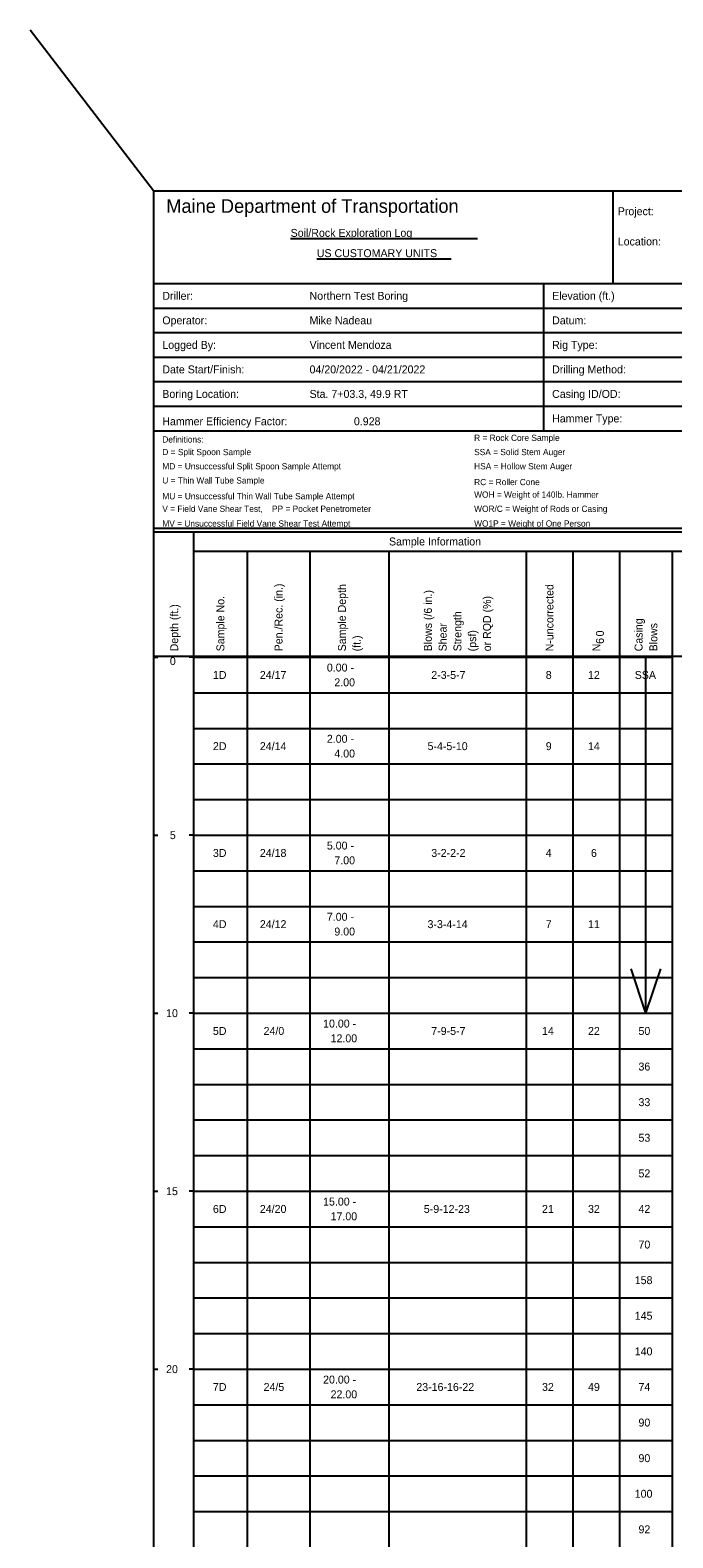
# Model space of a CAD drawing. Extents: x 9419 to 9552, y 6780 to 6865.
# Drawn here: x 9494.69 to 9512.73, y 6822.23 to 6864.58 of the extents above; entities that cross this region are included whole.
import ezdxf

# ---------------------------------------------------------------- set-up
doc = ezdxf.new("R2010")
doc.units = 0
doc.layers.add('7', color=7, linetype='Continuous')
doc.layers.add('JUNK', color=7, linetype='Continuous')

msp = doc.modelspace()

# ---------------------------------------------------------------- linework, layer by layer
at = {"layer": '7'}
for p, q in [((9502.002, 6858.729), (9507.244, 6858.729)), ((9502.736, 6858.16), (9506.51, 6858.16)), ((9511.973, 6836.968), (9511.973, 6846.968)), ((9511.973, 6836.968), (9511.556, 6838.218)), ((9511.973, 6836.968), (9512.389, 6838.218))]:
    msp.add_line(p, q, dxfattribs=at)
for points in [[(9498.158, 6860.072), (9498.158, 6821.941)], [(9498.158, 6860.072), (9529.654, 6860.072)], [(9511.04, 6860.072), (9511.04, 6857.463)], [(9498.158, 6857.463), (9529.654, 6857.463)], [(9509.095, 6857.463), (9509.095, 6854.018)], [(9498.158, 6856.774), (9529.654, 6856.774)], [(9498.158, 6856.085), (9529.654, 6856.085)], [(9498.158, 6855.396), (9529.654, 6855.396)], [(9498.158, 6854.707), (9529.654, 6854.707)], [(9498.158, 6854.018), (9529.654, 6854.018)], [(9509.095, 6854.018), (9509.095, 6853.328)], [(9498.158, 6853.328), (9529.654, 6853.328)], [(9498.158, 6850.59), (9529.654, 6850.59)], [(9498.158, 6850.486), (9529.654, 6850.486)], [(9499.276, 6850.486), (9499.276, 6821.941)], [(9499.276, 6849.95), (9514.023, 6849.95)], [(9500.785, 6849.95), (9500.785, 6821.941)], [(9502.54, 6849.95), (9502.54, 6821.941)], [(9504.755, 6849.95), (9504.755, 6821.941)], [(9508.61, 6849.95), (9508.61, 6821.941)], [(9509.922, 6849.95), (9509.922, 6821.941)], [(9511.234, 6849.95), (9511.234, 6821.941)], [(9512.711, 6849.95), (9512.711, 6821.941)], [(9498.158, 6846.996), (9529.654, 6846.996)], [(9498.158, 6846.968), (9498.279, 6846.968)], [(9499.276, 6846.968), (9499.154, 6846.968)], [(9499.276, 6846.968), (9500.785, 6846.968)], [(9500.785, 6846.968), (9502.54, 6846.968)], [(9502.54, 6846.968), (9504.755, 6846.968)], [(9504.755, 6846.968), (9508.61, 6846.968)], [(9508.61, 6846.968), (9509.922, 6846.968)], [(9509.922, 6846.968), (9511.234, 6846.968)], [(9511.234, 6846.968), (9512.711, 6846.968)], [(9499.276, 6845.968), (9500.785, 6845.968)], [(9500.785, 6845.968), (9502.54, 6845.968)], [(9502.54, 6845.968), (9504.755, 6845.968)], [(9504.755, 6845.968), (9508.61, 6845.968)], [(9508.61, 6845.968), (9509.922, 6845.968)], [(9509.922, 6845.968), (9511.234, 6845.968)], [(9511.234, 6845.968), (9512.711, 6845.968)], [(9499.276, 6844.968), (9500.785, 6844.968)], [(9500.785, 6844.968), (9502.54, 6844.968)], [(9502.54, 6844.968), (9504.755, 6844.968)], [(9504.755, 6844.968), (9508.61, 6844.968)], [(9508.61, 6844.968), (9509.922, 6844.968)], [(9509.922, 6844.968), (9511.234, 6844.968)], [(9511.234, 6844.968), (9512.711, 6844.968)], [(9499.276, 6843.968), (9500.785, 6843.968)], [(9500.785, 6843.968), (9502.54, 6843.968)], [(9502.54, 6843.968), (9504.755, 6843.968)], [(9504.755, 6843.968), (9508.61, 6843.968)], [(9508.61, 6843.968), (9509.922, 6843.968)], [(9509.922, 6843.968), (9511.234, 6843.968)], [(9511.234, 6843.968), (9512.711, 6843.968)], [(9499.276, 6842.968), (9500.785, 6842.968)], [(9500.785, 6842.968), (9502.54, 6842.968)], [(9502.54, 6842.968), (9504.755, 6842.968)], [(9504.755, 6842.968), (9508.61, 6842.968)], [(9508.61, 6842.968), (9509.922, 6842.968)], [(9509.922, 6842.968), (9511.234, 6842.968)], [(9511.234, 6842.968), (9512.711, 6842.968)], [(9498.158, 6841.968), (9498.279, 6841.968)], [(9499.276, 6841.968), (9499.154, 6841.968)], [(9499.276, 6841.968), (9500.785, 6841.968)], [(9500.785, 6841.968), (9502.54, 6841.968)], [(9502.54, 6841.968), (9504.755, 6841.968)], [(9504.755, 6841.968), (9508.61, 6841.968)], [(9508.61, 6841.968), (9509.922, 6841.968)], [(9509.922, 6841.968), (9511.234, 6841.968)], [(9511.234, 6841.968), (9512.711, 6841.968)], [(9499.276, 6840.968), (9500.785, 6840.968)], [(9500.785, 6840.968), (9502.54, 6840.968)], [(9502.54, 6840.968), (9504.755, 6840.968)], [(9504.755, 6840.968), (9508.61, 6840.968)], [(9508.61, 6840.968), (9509.922, 6840.968)], [(9509.922, 6840.968), (9511.234, 6840.968)], [(9511.234, 6840.968), (9512.711, 6840.968)], [(9499.276, 6839.968), (9500.785, 6839.968)], [(9500.785, 6839.968), (9502.54, 6839.968)], [(9502.54, 6839.968), (9504.755, 6839.968)], [(9504.755, 6839.968), (9508.61, 6839.968)], [(9508.61, 6839.968), (9509.922, 6839.968)], [(9509.922, 6839.968), (9511.234, 6839.968)], [(9511.234, 6839.968), (9512.711, 6839.968)], [(9499.276, 6838.968), (9500.785, 6838.968)], [(9500.785, 6838.968), (9502.54, 6838.968)], [(9502.54, 6838.968), (9504.755, 6838.968)], [(9504.755, 6838.968), (9508.61, 6838.968)], [(9508.61, 6838.968), (9509.922, 6838.968)], [(9509.922, 6838.968), (9511.234, 6838.968)], [(9511.234, 6838.968), (9512.711, 6838.968)], [(9499.276, 6837.968), (9500.785, 6837.968)], [(9500.785, 6837.968), (9502.54, 6837.968)], [(9502.54, 6837.968), (9504.755, 6837.968)], [(9504.755, 6837.968), (9508.61, 6837.968)], [(9508.61, 6837.968), (9509.922, 6837.968)], [(9509.922, 6837.968), (9511.234, 6837.968)], [(9511.234, 6837.968), (9512.711, 6837.968)], [(9498.158, 6836.968), (9498.279, 6836.968)], [(9499.276, 6836.968), (9499.154, 6836.968)], [(9499.276, 6836.968), (9500.785, 6836.968)], [(9500.785, 6836.968), (9502.54, 6836.968)], [(9502.54, 6836.968), (9504.755, 6836.968)], [(9504.755, 6836.968), (9508.61, 6836.968)], [(9508.61, 6836.968), (9509.922, 6836.968)], [(9509.922, 6836.968), (9511.234, 6836.968)], [(9511.234, 6836.968), (9512.711, 6836.968)], [(9499.276, 6835.968), (9500.785, 6835.968)], [(9500.785, 6835.968), (9502.54, 6835.968)], [(9502.54, 6835.968), (9504.755, 6835.968)], [(9504.755, 6835.968), (9508.61, 6835.968)], [(9508.61, 6835.968), (9509.922, 6835.968)], [(9509.922, 6835.968), (9511.234, 6835.968)], [(9511.234, 6835.968), (9512.711, 6835.968)], [(9499.276, 6834.968), (9500.785, 6834.968)], [(9500.785, 6834.968), (9502.54, 6834.968)], [(9502.54, 6834.968), (9504.755, 6834.968)], [(9504.755, 6834.968), (9508.61, 6834.968)], [(9508.61, 6834.968), (9509.922, 6834.968)], [(9509.922, 6834.968), (9511.234, 6834.968)], [(9511.234, 6834.968), (9512.711, 6834.968)], [(9499.276, 6833.968), (9500.785, 6833.968)], [(9500.785, 6833.968), (9502.54, 6833.968)], [(9502.54, 6833.968), (9504.755, 6833.968)], [(9504.755, 6833.968), (9508.61, 6833.968)], [(9508.61, 6833.968), (9509.922, 6833.968)], [(9509.922, 6833.968), (9511.234, 6833.968)], [(9511.234, 6833.968), (9512.711, 6833.968)], [(9499.276, 6832.968), (9500.785, 6832.968)], [(9500.785, 6832.968), (9502.54, 6832.968)], [(9502.54, 6832.968), (9504.755, 6832.968)], [(9504.755, 6832.968), (9508.61, 6832.968)], [(9508.61, 6832.968), (9509.922, 6832.968)], [(9509.922, 6832.968), (9511.234, 6832.968)], [(9511.234, 6832.968), (9512.711, 6832.968)], [(9498.158, 6831.968), (9498.279, 6831.968)], [(9499.276, 6831.968), (9499.154, 6831.968)], [(9499.276, 6831.968), (9500.785, 6831.968)], [(9500.785, 6831.968), (9502.54, 6831.968)], [(9502.54, 6831.968), (9504.755, 6831.968)], [(9504.755, 6831.968), (9508.61, 6831.968)], [(9508.61, 6831.968), (9509.922, 6831.968)], [(9509.922, 6831.968), (9511.234, 6831.968)], [(9511.234, 6831.968), (9512.711, 6831.968)], [(9499.276, 6830.968), (9500.785, 6830.968)], [(9500.785, 6830.968), (9502.54, 6830.968)], [(9502.54, 6830.968), (9504.755, 6830.968)], [(9504.755, 6830.968), (9508.61, 6830.968)], [(9508.61, 6830.968), (9509.922, 6830.968)], [(9509.922, 6830.968), (9511.234, 6830.968)], [(9511.234, 6830.968), (9512.711, 6830.968)], [(9499.276, 6829.968), (9500.785, 6829.968)], [(9500.785, 6829.968), (9502.54, 6829.968)], [(9502.54, 6829.968), (9504.755, 6829.968)], [(9504.755, 6829.968), (9508.61, 6829.968)], [(9508.61, 6829.968), (9509.922, 6829.968)], [(9509.922, 6829.968), (9511.234, 6829.968)], [(9511.234, 6829.968), (9512.711, 6829.968)], [(9499.276, 6828.968), (9500.785, 6828.968)], [(9500.785, 6828.968), (9502.54, 6828.968)], [(9502.54, 6828.968), (9504.755, 6828.968)], [(9504.755, 6828.968), (9508.61, 6828.968)], [(9508.61, 6828.968), (9509.922, 6828.968)], [(9509.922, 6828.968), (9511.234, 6828.968)], [(9511.234, 6828.968), (9512.711, 6828.968)], [(9499.276, 6827.968), (9500.785, 6827.968)], [(9500.785, 6827.968), (9502.54, 6827.968)], [(9502.54, 6827.968), (9504.755, 6827.968)], [(9504.755, 6827.968), (9508.61, 6827.968)], [(9508.61, 6827.968), (9509.922, 6827.968)], [(9509.922, 6827.968), (9511.234, 6827.968)], [(9511.234, 6827.968), (9512.711, 6827.968)], [(9498.158, 6826.968), (9498.279, 6826.968)], [(9499.276, 6826.968), (9499.154, 6826.968)], [(9499.276, 6826.968), (9500.785, 6826.968)], [(9500.785, 6826.968), (9502.54, 6826.968)], [(9502.54, 6826.968), (9504.755, 6826.968)], [(9504.755, 6826.968), (9508.61, 6826.968)], [(9508.61, 6826.968), (9509.922, 6826.968)], [(9509.922, 6826.968), (9511.234, 6826.968)], [(9511.234, 6826.968), (9512.711, 6826.968)], [(9499.276, 6825.968), (9500.785, 6825.968)], [(9500.785, 6825.968), (9502.54, 6825.968)], [(9502.54, 6825.968), (9504.755, 6825.968)], [(9504.755, 6825.968), (9508.61, 6825.968)], [(9508.61, 6825.968), (9509.922, 6825.968)], [(9509.922, 6825.968), (9511.234, 6825.968)], [(9511.234, 6825.968), (9512.711, 6825.968)], [(9499.276, 6824.968), (9500.785, 6824.968)], [(9500.785, 6824.968), (9502.54, 6824.968)], [(9502.54, 6824.968), (9504.755, 6824.968)], [(9504.755, 6824.968), (9508.61, 6824.968)], [(9508.61, 6824.968), (9509.922, 6824.968)], [(9509.922, 6824.968), (9511.234, 6824.968)], [(9511.234, 6824.968), (9512.711, 6824.968)], [(9499.276, 6823.968), (9500.785, 6823.968)], [(9500.785, 6823.968), (9502.54, 6823.968)], [(9502.54, 6823.968), (9504.755, 6823.968)], [(9504.755, 6823.968), (9508.61, 6823.968)], [(9508.61, 6823.968), (9509.922, 6823.968)], [(9509.922, 6823.968), (9511.234, 6823.968)], [(9511.234, 6823.968), (9512.711, 6823.968)], [(9499.276, 6822.968), (9500.785, 6822.968)], [(9500.785, 6822.968), (9502.54, 6822.968)], [(9502.54, 6822.968), (9504.755, 6822.968)], [(9504.755, 6822.968), (9508.61, 6822.968)], [(9508.61, 6822.968), (9509.922, 6822.968)], [(9509.922, 6822.968), (9511.234, 6822.968)], [(9511.234, 6822.968), (9512.711, 6822.968)]]:
    msp.add_lwpolyline(points, dxfattribs=at)
at = {"layer": 'JUNK'}
msp.add_line((9498.158, 6860.072), (9494.693, 6864.581), dxfattribs=at)

# ---------------------------------------------------------------- texts
at = {"layer": '7'}
for s, height, p in [('Maine Department of Transportation', 0.38194, (9498.512, 6859.45)), ('Project:', 0.2228, (9511.182, 6859.382)), ('Soil/Rock Exploration Log', 0.2228, (9502.002, 6858.775)), ('Location:', 0.2228, (9511.182, 6858.533)), ('US CUSTOMARY UNITS', 0.2228, (9502.736, 6858.205)), ('Driller:', 0.2228, (9498.401, 6857.007)), ('Northern Test Boring', 0.2228, (9502.533, 6857.007)), ('Elevation (ft.)', 0.2228, (9509.339, 6857.007)), ('Operator:', 0.2228, (9498.401, 6856.318)), ('Mike Nadeau', 0.2228, (9502.533, 6856.318)), ('Datum:', 0.2228, (9509.339, 6856.318)), ('Logged By:', 0.2228, (9498.401, 6855.629)), ('Vincent Mendoza', 0.2228, (9502.533, 6855.629)), ('Rig Type:', 0.2228, (9509.339, 6855.629)), ('Date Start/Finish:', 0.2228, (9498.401, 6854.94)), ('04/20/2022 - 04/21/2022', 0.2228, (9502.533, 6854.94)), ('Drilling Method:', 0.2228, (9509.339, 6854.94)), ('Boring Location:', 0.2228, (9498.401, 6854.251)), ('Sta. 7+03.3, 49.9 RT', 0.2228, (9502.533, 6854.251)), ('Casing ID/OD:', 0.2228, (9509.339, 6854.251)), ('Hammer Efficiency Factor:', 0.2228, (9498.401, 6853.482)), ('0.928', 0.2228, (9503.777, 6853.482)), ('Hammer Type:', 0.2228, (9509.339, 6853.562)), ('Definitions:', 0.17506, (9498.401, 6852.996)), ('D = Split Spoon Sample', 0.17506, (9498.401, 6852.643)), ('SSA = Solid Stem Auger', 0.17506, (9507.151, 6852.643)), ('R = Rock Core Sample', 0.17506, (9507.151, 6853.042)), ('MD = Unsuccessful Split Spoon Sample Attempt', 0.17506, (9498.401, 6852.244)), ('HSA = Hollow Stem Auger', 0.17506, (9507.151, 6852.244)), ('U = Thin Wall Tube Sample', 0.17506, (9498.401, 6851.846)), ('RC = Roller Cone', 0.17506, (9507.151, 6851.8)), ('MU = Unsuccessful Thin Wall Tube Sample Attempt', 0.17506, (9498.401, 6851.402)), ('WOH = Weight of 140lb. Hammer', 0.17506, (9507.151, 6851.447)), ('V = Field Vane Shear Test,    PP = Pocket Penetrometer', 0.17506, (9498.401, 6851.049)), ('WOR/C = Weight of Rods or Casing', 0.17506, (9507.151, 6851.049)), ('MV = Unsuccessful Field Vane Shear Test Attempt', 0.17506, (9498.401, 6850.635)), ('WO1P = Weight of One Person', 0.17506, (9507.151, 6850.635)), ('Sample Information', 0.2228, (9504.762, 6850.106)), ('0', 0.223, (9498.612, 6846.746)), ('1D', 0.2228, (9499.821, 6846.357)), ('24/17', 0.2228, (9501.138, 6846.357)), ('0.00 -', 0.2228, (9503.018, 6846.564)), ('2-3-5-7', 0.2228, (9505.948, 6846.357)), ('8', 0.223, (9509.161, 6846.357)), (' 12', 0.2228, (9510.264, 6846.357)), ('SSA', 0.2228, (9511.658, 6846.357)), ('2.00', 0.2228, (9503.228, 6846.15)), ('2.00 -', 0.2228, (9503.018, 6844.564)), ('2D', 0.2228, (9499.821, 6844.357)), ('24/14', 0.2228, (9501.138, 6844.357)), ('4.00', 0.2228, (9503.228, 6844.15)), ('5-4-5-10', 0.2228, (9505.843, 6844.357)), ('9', 0.223, (9509.161, 6844.357)), (' 14', 0.2228, (9510.264, 6844.357)), ('5', 0.223, (9498.612, 6841.857)), ('3D', 0.2228, (9499.821, 6841.357)), ('24/18', 0.2228, (9501.138, 6841.357)), ('5.00 -', 0.2228, (9503.018, 6841.564)), ('7.00', 0.2228, (9503.228, 6841.15)), ('3-2-2-2', 0.2228, (9505.948, 6841.357)), ('4', 0.223, (9509.161, 6841.357)), ('  6', 0.2228, (9510.264, 6841.357)), ('7.00 -', 0.2228, (9503.018, 6839.564)), ('4D', 0.2228, (9499.821, 6839.357)), ('24/12', 0.2228, (9501.138, 6839.357)), ('9.00', 0.2228, (9503.228, 6839.15)), ('3-3-4-14', 0.2228, (9505.843, 6839.357)), ('7', 0.223, (9509.161, 6839.357)), (' 11', 0.2228, (9510.264, 6839.357)), ('10', 0.2228, (9498.507, 6836.857)), ('10.00 -', 0.2228, (9502.913, 6836.564)), ('5D', 0.2228, (9499.821, 6836.357)), ('24/0', 0.2228, (9501.243, 6836.357)), ('12.00', 0.2228, (9503.123, 6836.15)), ('7-9-5-7', 0.2228, (9505.948, 6836.357)), ('14', 0.2228, (9509.056, 6836.357)), (' 22', 0.2228, (9510.264, 6836.357)), ('50', 0.2228, (9511.763, 6836.357)), ('36', 0.2228, (9511.763, 6835.357)), ('33', 0.2228, (9511.763, 6834.357)), ('53', 0.2228, (9511.763, 6833.357)), ('52', 0.2228, (9511.763, 6832.357)), ('15', 0.2228, (9498.507, 6831.857)), ('15.00 -', 0.2228, (9502.913, 6831.564)), ('6D', 0.2228, (9499.821, 6831.357)), ('24/20', 0.2228, (9501.138, 6831.357)), ('17.00', 0.2228, (9503.123, 6831.15)), ('5-9-12-23', 0.2228, (9505.739, 6831.357)), ('21', 0.2228, (9509.056, 6831.357)), (' 32', 0.2228, (9510.264, 6831.357)), ('42', 0.2228, (9511.763, 6831.357)), ('70', 0.2228, (9511.763, 6830.357)), ('158', 0.2228, (9511.658, 6829.357)), ('145', 0.2228, (9511.658, 6828.357)), ('140', 0.2228, (9511.658, 6827.357)), ('20', 0.2228, (9498.507, 6826.857)), ('7D', 0.2228, (9499.821, 6826.357)), ('24/5', 0.2228, (9501.243, 6826.357)), ('20.00 -', 0.2228, (9502.913, 6826.564)), ('23-16-16-22', 0.2228, (9505.529, 6826.357)), ('32', 0.2228, (9509.056, 6826.357)), (' 49', 0.2228, (9510.264, 6826.357)), ('74', 0.2228, (9511.763, 6826.357)), ('22.00', 0.2228, (9503.123, 6826.15)), ('90', 0.2228, (9511.763, 6825.357)), ('90', 0.2228, (9511.763, 6824.357)), ('100', 0.2228, (9511.658, 6823.357)), ('92', 0.2228, (9511.763, 6822.357))]:
    msp.add_text(s, height=height, dxfattribs=at).set_placement(p)
for s, height, p in [('Pen./Rec. (in.)', 0.2228, (9501.774, 6847.132)), ('Sample Depth', 0.2228, (9503.552, 6847.132)), ('N-uncorrected', 0.2228, (9509.377, 6847.132)), ('Sample No.', 0.2228, (9500.142, 6847.132)), ('Blows (/6 in.)', 0.2228, (9505.965, 6847.132)), ('or RQD (%%%)', 0.2228, (9507.622, 6847.132)), ('Depth (ft.)', 0.2228, (9498.846, 6847.132)), ('Strength', 0.2228, (9506.794, 6847.132)), ('Shear', 0.2228, (9506.379, 6847.132)), ('Casing ', 0.2228, (9511.877, 6847.132)), ('Blows', 0.2228, (9512.291, 6847.132)), ('(ft.)', 0.2228, (9503.966, 6847.132)), ('(psf)', 0.2228, (9507.208, 6847.132)), ('N', 0.223, (9510.69, 6847.132)), ('0', 0.223, (9510.793, 6847.552)), ('6', 0.223, (9510.793, 6847.342))]:
    msp.add_text(s, height=height, rotation=90, dxfattribs=at).set_placement(p)

doc.saveas('drawing.dxf')
